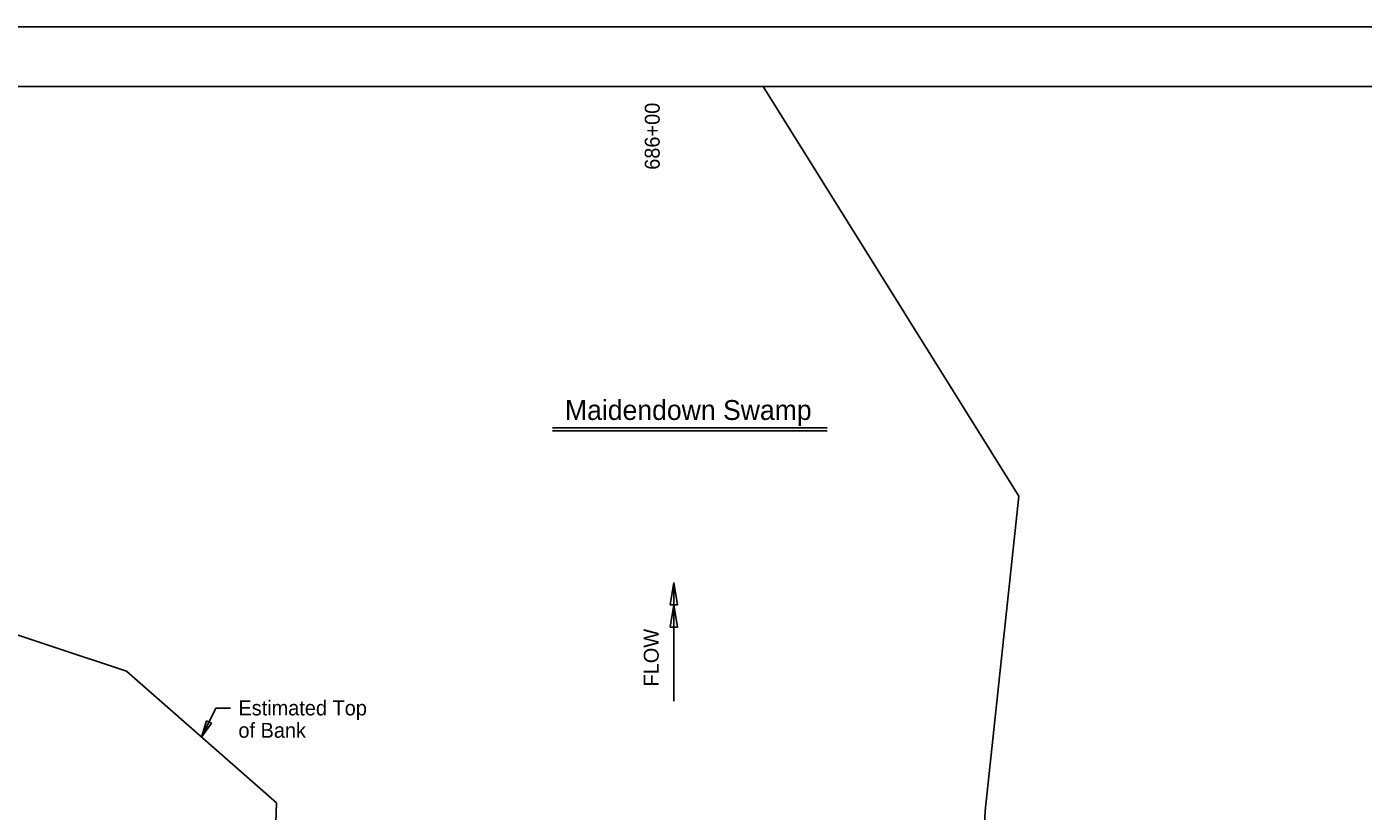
# Model space of a CAD drawing. Extents: x -463 to -191, y 251 to 416.
# Drawn here: x -363.8 to -279.7, y 367.1 to 416.4 of the extents above; entities that cross this region are included whole.
import ezdxf

# ---------------------------------------------------------------- set-up
doc = ezdxf.new("R2010")
doc.units = 0
for name, color, linetype in [('BR_AUTO DIMENSION', 7, 'Continuous'), ('BR_BORDER LINES', 7, 'Continuous'), ('BR_TEXT', 7, 'Continuous'), ('Default', 7, 'Continuous'), ('RD_SHT_IplotShp', 7, 'Continuous')]:
    doc.layers.add(name, color=color, linetype=linetype)

msp = doc.modelspace()

# ---------------------------------------------------------------- linework, layer by layer
at = {"layer": 'BR_AUTO DIMENSION'}
for p, q in [((-323.313, 380.099), (-323.079, 381.505)), ((-323.079, 374.048), (-323.079, 381.505)), ((-323.079, 381.505), (-322.843, 380.099)), ((-322.843, 380.099), (-323.313, 380.099)), ((-323.313, 378.692), (-323.079, 380.099)), ((-323.079, 380.099), (-322.843, 378.692)), ((-322.843, 378.692), (-323.313, 378.692)), ((-351.887, 373.604), (-352.798, 371.786)), ((-350.977, 373.604), (-351.887, 373.604)), ((-350.977, 373.604), (-351.887, 373.604)), ((-352.483, 372.808), (-352.798, 371.786)), ((-352.798, 371.786), (-352.168, 372.65)), ((-352.168, 372.65), (-352.483, 372.808))]:
    msp.add_line(p, q, dxfattribs=at)
at = {"layer": 'BR_BORDER LINES'}
for p, q in [((-462.879, 416.448), (-192.879, 416.448)), ((-196.63, 412.688), (-449.129, 412.688))]:
    msp.add_line(p, q, dxfattribs=at)
at = {"layer": 'BR_TEXT'}
for p, q in [((-330.712, 391.218), (-313.428, 391.218)), ((-330.712, 391.031), (-313.428, 391.031))]:
    msp.add_line(p, q, dxfattribs=at)
at = {"layer": 'Default'}
for points in [[(-303.675, 363.498), (-303.507, 367.154), (-303.507, 367.154), (-301.373, 386.924), (-317.47, 412.688)], [(-350.569, 293.783), (-348.075, 367.639), (-357.521, 375.932), (-398.853, 389.643)]]:
    msp.add_lwpolyline(points, dxfattribs=at)
at = {"layer": 'RD_SHT_IplotShp'}
msp.add_lwpolyline([(-462.879, 416.438), (-192.879, 416.438), (-192.879, 251.438), (-462.879, 251.438)], close=True, dxfattribs=at)

# ---------------------------------------------------------------- texts
at = {"layer": 'BR_AUTO DIMENSION'}
msp.add_text('686+00', height=0.9375, rotation=90, dxfattribs=at).set_placement((-323.971, 407.454))
at = {"layer": 'BR_TEXT'}
for s, height, p in [('Maidendown Swamp', 1.25, (-329.931, 391.723)), ('Estimated Top', 0.9375, (-350.473, 373.145)), ('of Bank', 0.9375, (-350.473, 371.739))]:
    msp.add_text(s, height=height, dxfattribs=at).set_placement(p)
msp.add_text('FLOW', height=0.9375, rotation=90, dxfattribs=at).set_placement((-324.036, 374.964))

doc.saveas('drawing.dxf')
